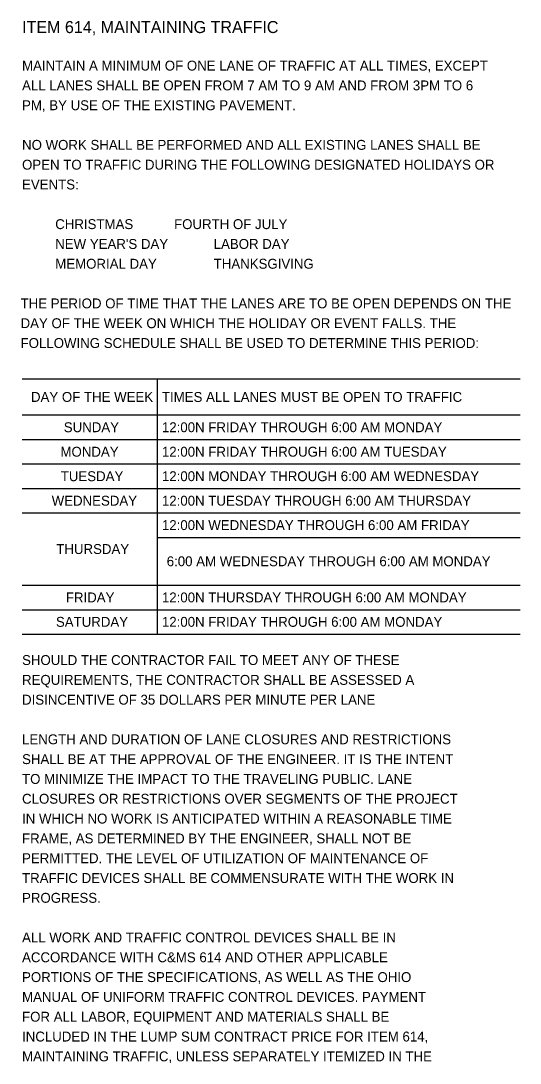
# Model space of a CAD drawing. Extents: x -57 to 92, y -15 to 47.
# Drawn here: x -29.92 to -22.86, y 4.75 to 19.48 of the extents above; entities that cross this region are included whole.
import ezdxf

# ---------------------------------------------------------------- set-up
doc = ezdxf.new("R2010")
doc.units = 0
doc.layers.add('SH_Data', color=7, linetype='Continuous')
doc.layers.add('SH_Text', color=7, linetype='Continuous')

msp = doc.modelspace()

# ---------------------------------------------------------------- linework, layer by layer
at = {"layer": 'SH_Data'}
for p, q in [((-29.903, 14.423), (-22.862, 14.423)), ((-27.992, 14.423), (-27.992, 10.816)), ((-27.992, 14.423), (-27.992, 10.816)), ((-29.903, 13.912), (-22.862, 13.912)), ((-29.903, 13.912), (-22.862, 13.912)), ((-29.903, 13.566), (-22.862, 13.566)), ((-29.903, 13.566), (-22.862, 13.566)), ((-29.903, 13.22), (-22.862, 13.22)), ((-29.903, 13.22), (-22.862, 13.22)), ((-29.903, 12.874), (-22.862, 12.874)), ((-29.903, 12.874), (-22.862, 12.874)), ((-29.903, 12.529), (-22.862, 12.529)), ((-29.903, 12.529), (-22.862, 12.529)), ((-27.992, 12.183), (-22.862, 12.183)), ((-27.992, 12.183), (-22.862, 12.183)), ((-29.903, 11.507), (-22.862, 11.507)), ((-29.903, 11.507), (-22.862, 11.507)), ((-29.903, 11.161), (-22.862, 11.161)), ((-29.903, 11.161), (-22.862, 11.161)), ((-29.903, 10.816), (-22.862, 10.816)), ((-29.903, 10.816), (-22.862, 10.816))]:
    msp.add_line(p, q, dxfattribs=at)

# ---------------------------------------------------------------- texts
at = {"layer": 'SH_Text'}
for s, height, p in [('ITEM 614, MAINTAINING TRAFFIC', 0.17, (-29.903, 19.309)), ('MAINTAIN A MINIMUM OF ONE LANE OF TRAFFIC AT ALL TIMES, EXCEPT ', 0.14, (-29.903, 18.779)), ('ALL LANES SHALL BE OPEN FROM 7 AM TO 9 AM AND FROM 3PM TO 6 ', 0.14, (-29.903, 18.499)), ('PM, BY USE OF THE EXISTING PAVEMENT.', 0.14, (-29.903, 18.219)), ('NO WORK SHALL BE PERFORMED AND ALL EXISTING LANES SHALL BE ', 0.14, (-29.903, 17.659)), ('OPEN TO TRAFFIC DURING THE FOLLOWING DESIGNATED HOLIDAYS OR ', 0.14, (-29.903, 17.379)), ('EVENTS:', 0.14, (-29.903, 17.099)), ('CHRISTMAS', 0.14, (-29.434, 16.539)), ('FOURTH OF JULY', 0.14, (-27.754, 16.539)), ("NEW YEAR'S DAY", 0.14, (-29.434, 16.259)), ('LABOR DAY', 0.14, (-27.194, 16.259)), ('MEMORIAL DAY', 0.14, (-29.434, 15.979)), ('THANKSGIVING', 0.14, (-27.194, 15.979)), ('THE PERIOD OF TIME THAT THE LANES ARE TO BE OPEN DEPENDS ON THE ', 0.14, (-29.924, 15.419)), ('DAY OF THE WEEK ON WHICH THE HOLIDAY OR EVENT FALLS. THE ', 0.14, (-29.924, 15.139)), ('FOLLOWING SCHEDULE SHALL BE USED TO DETERMINE THIS PERIOD:', 0.14, (-29.924, 14.859)), ('DAY OF THE WEEK', 0.14, (-29.777, 14.097)), ('TIMES ALL LANES MUST BE OPEN TO TRAFFIC', 0.14, (-27.926, 14.097)), ('SUNDAY', 0.14, (-29.313, 13.669)), ('12:00N FRIDAY THROUGH 6:00 AM MONDAY', 0.14, (-27.926, 13.669)), ('MONDAY', 0.14, (-29.36, 13.323)), ('12:00N FRIDAY THROUGH 6:00 AM TUESDAY', 0.14, (-27.926, 13.323)), ('TUESDAY', 0.14, (-29.356, 12.977)), ('12:00N MONDAY THROUGH 6:00 AM WEDNESDAY', 0.14, (-27.926, 12.977)), ('WEDNESDAY', 0.14, (-29.484, 12.631)), ('12:00N TUESDAY THROUGH 6:00 AM THURSDAY', 0.14, (-27.926, 12.631)), ('12:00N WEDNESDAY THROUGH 6:00 AM FRIDAY', 0.14, (-27.926, 12.286)), ('THURSDAY', 0.14, (-29.419, 11.948)), ('6:00 AM WEDNESDAY THROUGH 6:00 AM MONDAY', 0.14, (-27.858, 11.775)), ('FRIDAY', 0.14, (-29.284, 11.264)), ('12:00N THURSDAY THROUGH 6:00 AM MONDAY', 0.14, (-27.926, 11.264)), ('SATURDAY', 0.14, (-29.424, 10.919)), ('12:00N FRIDAY THROUGH 6:00 AM MONDAY', 0.14, (-27.926, 10.919)), ('SHOULD THE CONTRACTOR FAIL TO MEET ANY OF THESE', 0.14, (-29.903, 10.379)), ('REQUIREMENTS, THE CONTRACTOR SHALL BE ASSESSED A', 0.14, (-29.903, 10.099)), ('DISINCENTIVE OF 35 DOLLARS PER MINUTE PER LANE', 0.14, (-29.903, 9.819)), ('LENGTH AND DURATION OF LANE CLOSURES AND RESTRICTIONS', 0.14, (-29.903, 9.259)), ('SHALL BE AT THE APPROVAL OF THE ENGINEER. IT IS THE INTENT', 0.14, (-29.903, 8.979)), ('TO MINIMIZE THE IMPACT TO THE TRAVELING PUBLIC. LANE', 0.14, (-29.903, 8.699)), ('CLOSURES OR RESTRICTIONS OVER SEGMENTS OF THE PROJECT', 0.14, (-29.903, 8.419)), ('IN WHICH NO WORK IS ANTICIPATED WITHIN A REASONABLE TIME', 0.14, (-29.903, 8.139)), ('FRAME, AS DETERMINED BY THE ENGINEER, SHALL NOT BE', 0.14, (-29.903, 7.859)), ('PERMITTED. THE LEVEL OF UTILIZATION OF MAINTENANCE OF', 0.14, (-29.903, 7.579)), ('TRAFFIC DEVICES SHALL BE COMMENSURATE WITH THE WORK IN', 0.14, (-29.903, 7.299)), ('PROGRESS.', 0.14, (-29.903, 7.019)), ('ALL WORK AND TRAFFIC CONTROL DEVICES SHALL BE IN', 0.14, (-29.903, 6.459)), ('ACCORDANCE WITH C&MS 614 AND OTHER APPLICABLE', 0.14, (-29.903, 6.179)), ('PORTIONS OF THE SPECIFICATIONS, AS WELL AS THE OHIO', 0.14, (-29.903, 5.899)), ('MANUAL OF UNIFORM TRAFFIC CONTROL DEVICES. PAYMENT', 0.14, (-29.903, 5.619)), ('FOR ALL LABOR, EQUIPMENT AND MATERIALS SHALL BE', 0.14, (-29.903, 5.339)), ('INCLUDED IN THE LUMP SUM CONTRACT PRICE FOR ITEM 614,', 0.14, (-29.903, 5.059)), ('MAINTAINING TRAFFIC, UNLESS SEPARATELY ITEMIZED IN THE', 0.14, (-29.903, 4.779))]:
    msp.add_text(s, height=height, dxfattribs=at).set_placement(p)

doc.saveas('drawing.dxf')
